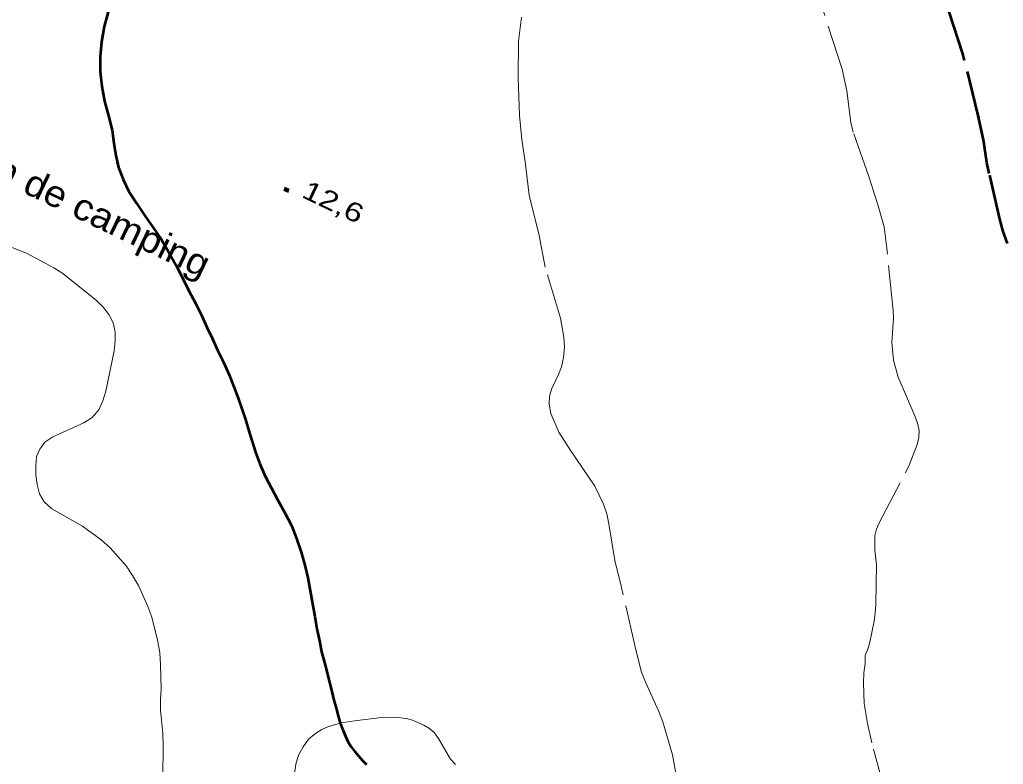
# Model space of a CAD drawing. Extents: x 355726 to 357533, y 5103782 to 5105258.
# Drawn here: x 356261.4 to 356339.7, y 5104714.5 to 5104773.8 of the extents above; entities that cross this region are included whole.
import ezdxf

# ---------------------------------------------------------------- set-up
doc = ezdxf.new("R2010")
doc.units = 0
doc.header["$LTSCALE"] = 0.6
for name, pattern in [('DASH_DOUBLE_DOT', [9.2, 5, -1.2, 0.3, -1.2, 0.3, -1.2]), ('LONG_DASH_SHORT_DASH', [9.9, 6, -1.2, 1.5, -1.2]), ('LONG_DASHED', [7.5, 6, -1.5])]:
    doc.linetypes.add(name, pattern=pattern)
for name, color, linetype, lineweight in [('1', 7, 'LONG_DASHED', 53), ('2', 7, 'LONG_DASHED', 13), ('3', 7, 'Continuous', 140), ('4', 7, 'DASH_DOUBLE_DOT', 53), ('56', 7, 'LONG_DASH_SHORT_DASH', 25)]:
    doc.layers.add(name, color=color, linetype=linetype, lineweight=lineweight)

msp = doc.modelspace()

# ---------------------------------------------------------------- linework, layer by layer
at = {"layer": '1'}
msp.add_lwpolyline([(356340.04, 5104755.94), (356339.71, 5104756.9), (356339.44, 5104757.88), (356338.6, 5104761.51), (356338.41, 5104762.4), (356338.14, 5104764.21), (356337.72, 5104766.15), (356336.5, 5104771.05), (356335.3, 5104774.72), (356333.79, 5104778.37), (356332.61, 5104782.18), (356332.15, 5104783.84), (356331.22, 5104786.34), (356330.93, 5104787.25), (356330.72, 5104788.17), (356329.92, 5104792.88), (356329.7, 5104793.78), (356328.8, 5104796.55), (356328.55, 5104797.55)], dxfattribs=at)
at = {"layer": '2'}
for points in [[(356329.48, 5104732.68), (356329.61, 5104733.21), (356329.84, 5104733.7), (356332.23, 5104738.3), (356332.86, 5104739.95), (356333, 5104740.51), (356333.01, 5104741.07), (356332.87, 5104741.65), (356332.66, 5104742.23), (356331.34, 5104745.32), (356330.96, 5104746.66), (356330.84, 5104748.08), (356330.97, 5104750.01), (356330.93, 5104750.62), (356330.44, 5104755.58), (356330.22, 5104757.28), (356329.75, 5104758.96), (356329.01, 5104761.29), (356327.76, 5104764.82), (356327.57, 5104765.59), (356327.25, 5104768.11), (356326.88, 5104769.83), (356324.44, 5104777.38)], [(356303.59, 5104743.8), (356303.75, 5104744.4), (356304.29, 5104745.51), (356304.54, 5104746.13), (356304.69, 5104746.88), (356304.76, 5104747.69), (356304.72, 5104748.48), (356304.44, 5104750.01), (356303.24, 5104754.07), (356302.76, 5104756.59), (356301.95, 5104759.8), (356301.65, 5104762.44), (356301.37, 5104764.24), (356301.18, 5104766.13), (356301.09, 5104769.15), (356301.12, 5104772.05), (356301.36, 5104773.98)], [(356260.36, 5104755.79), (356261.94, 5104755.18), (356264.1, 5104754.01), (356264.82, 5104753.57), (356267.51, 5104751.42), (356268.07, 5104750.86), (356268.5, 5104750.29), (356268.82, 5104749.63), (356268.98, 5104748.93), (356269, 5104748.19), (356268.92, 5104747.41), (356268.26, 5104744.2), (356268.02, 5104743.43), (356267.68, 5104742.71), (356267.17, 5104742.09), (356266.5, 5104741.67), (356264.02, 5104740.55), (356263.38, 5104740.13), (356262.99, 5104739.58), (356262.74, 5104738.98), (356262.67, 5104738.26), (356262.68, 5104737.53), (356262.79, 5104736.76), (356262.97, 5104736.03), (356263.33, 5104735.38), (356263.96, 5104734.83), (356266.39, 5104733.45), (356267.89, 5104732.37), (356268.59, 5104731.72), (356269.87, 5104730.29), (356270.38, 5104729.53), (356270.84, 5104728.72), (356271.6, 5104727.05), (356271.92, 5104726.21), (356272.36, 5104724.38), (356272.54, 5104723.4), (356272.6, 5104722.41), (356272.65, 5104720.48), (356272.6, 5104719.66), (356272.61, 5104718.8), (356272.78, 5104716.93), (356272.82, 5104715.98), (356272.79, 5104713.43)], [(356313.86, 5104712.61), (356313.37, 5104715.25), (356312.59, 5104717.88), (356312.29, 5104718.68), (356311.24, 5104720.98), (356310.91, 5104721.82), (356310.44, 5104723.59), (356309.32, 5104728.55), (356308.79, 5104730.7), (356308.31, 5104733.63), (356308.13, 5104734.43), (356307.88, 5104735.2), (356307.18, 5104736.62), (356305.22, 5104739.51), (356304.32, 5104740.94), (356303.69, 5104742.42), (356303.56, 5104743.16), (356303.59, 5104743.8)], [(356330.33, 5104712.22), (356329.25, 5104716.19), (356328.89, 5104717.73), (356328.63, 5104719.32), (356328.57, 5104720.98), (356328.61, 5104721.76), (356328.71, 5104722.49), (356328.71, 5104723.16), (356328.96, 5104723.73), (356329.09, 5104724.2), (356329.43, 5104725.87), (356329.5, 5104726.51), (356329.55, 5104727.17), (356329.61, 5104730.38), (356329.47, 5104731.55), (356329.48, 5104732.68)], [(356296.09, 5104714.47), (356295.69, 5104714.9), (356294.75, 5104716.53), (356294.42, 5104716.99), (356294.03, 5104717.34), (356293.58, 5104717.59), (356292.66, 5104717.99), (356292.2, 5104718.13), (356291.25, 5104718.25), (356290.21, 5104718.2), (356288.04, 5104717.96), (356287.01, 5104717.79), (356285.99, 5104717.49), (356285.46, 5104717.26), (356284.95, 5104716.93), (356284.4, 5104716.48), (356283.96, 5104715.88), (356283.6, 5104715.22), (356283.39, 5104714.5), (356283.26, 5104713.75)]]:
    msp.add_lwpolyline(points, dxfattribs=at)
at = {"layer": '3'}
msp.add_line((356282.46, 5104760.31), (356282.82, 5104760.14), dxfattribs=at)
at = {"layer": '4'}
for points in [[(356268.43, 5104774.4), (356268.12, 5104773.23), (356267.91, 5104772.01), (356267.81, 5104770.83), (356267.81, 5104769.63), (356267.92, 5104768.46), (356268.13, 5104767.28), (356268.46, 5104766.11), (356268.75, 5104764.96), (356268.89, 5104763.94), (356269.04, 5104762.96), (356269.27, 5104762), (356269.62, 5104761.04), (356270.08, 5104760.09), (356270.68, 5104759.15), (356271.32, 5104758.2), (356272, 5104757.24), (356272.66, 5104756.29), (356273.25, 5104755.28), (356273.83, 5104754.26), (356274.36, 5104753.21), (356274.87, 5104752.18), (356275.39, 5104751.21), (356275.86, 5104750.25), (356276.29, 5104749.3), (356276.75, 5104748.36), (356277.18, 5104747.41), (356277.64, 5104746.46), (356278.06, 5104745.49), (356278.44, 5104744.54), (356278.78, 5104743.63), (356279.09, 5104742.78), (356279.37, 5104741.95), (356279.6, 5104741.11), (356279.87, 5104740.26), (356280.16, 5104739.34), (356280.52, 5104738.4), (356280.94, 5104737.43), (356281.43, 5104736.48), (356281.95, 5104735.51), (356282.51, 5104734.51), (356283.02, 5104733.5), (356283.43, 5104732.46), (356283.8, 5104731.38), (356284.09, 5104730.34), (356284.33, 5104729.33), (356284.52, 5104728.3), (356284.7, 5104727.26), (356284.89, 5104726.25), (356285.06, 5104725.26), (356285.25, 5104724.32), (356285.43, 5104723.45), (356285.65, 5104722.59)], [(356285.65, 5104722.59), (356285.86, 5104721.76), (356286.07, 5104720.99), (356286.25, 5104720.28), (356286.41, 5104719.58), (356286.58, 5104718.95), (356286.74, 5104718.34), (356286.91, 5104717.76), (356287.11, 5104717.22), (356287.33, 5104716.72), (356287.54, 5104716.26), (356287.79, 5104715.87), (356288.08, 5104715.5), (356288.38, 5104715.16), (356288.69, 5104714.8), (356289, 5104714.48)]]:
    msp.add_lwpolyline(points, dxfattribs=at)

# ---------------------------------------------------------------- texts
at = {"layer": '3', "width": 1.3}
msp.add_text('12,6   ', height=1.5, rotation=334.423, dxfattribs=at).set_placement((356283.75, 5104759.68))
at = {"layer": '56', "width": 1.1}
msp.add_text('Terrain de camping', height=2.1, rotation=334.42, dxfattribs=at).set_placement((356251.91, 5104764.67))

doc.saveas('drawing.dxf')
